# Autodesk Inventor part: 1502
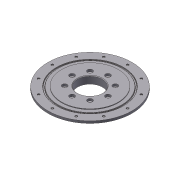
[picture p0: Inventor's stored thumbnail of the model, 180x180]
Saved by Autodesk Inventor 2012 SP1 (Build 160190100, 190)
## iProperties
Created: 2012-02
Part Number: 1502
Material: Aluminum-6061
Document SubType Name: Modeling
Designer: LACO
Density: 2.71 g/cm^3
Mass: 1442.59 g
Surface Area: 1107.25 cm^2
Volume: 532.323 cm^3
Author: LACO
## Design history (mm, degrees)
sketch "Sketch1"
  geometry: L1 (0, 0)-(-139.7, 0); L2 (-120.65, -8.382)-(-60.96, -8.382); L3 (-60.96, -8.382)-(-60.96, -21.082); L4 (-60.96, -21.082)-(-35.56, -21.082); L5 (-35.56, -21.082)-(-35.56, 0); L6 (0, 0)-(0, -15.838); L7 (-120.65, -8.382)-(-120.65, -2.032); L8 (-120.65, -2.032)-(-81.153, -2.032); L9 (-81.153, -2.032)-(-81.153, 0); L10 (-35.56, 0)-(-81.153, 0)
  constraints: 20 end point, 4 perpendicular, 3 parallel, 2 point on line, 1 horizontal
  dimensions: "d1" = 71.12 diameter of L5 L6; "d2" = 121.92 diameter of L3 L6; "d4" = 12.7 distance between parallel lines of L4 L2; "d6" = 2.032 distance between parallel lines of L8 L1; "d7" = 162.306 diameter of L9 L6; "d8" = 241.3 diameter of L7 L6; "d38" = 6.35 distance between parallel lines of L2 L8
revolve "Revolution1" sketch "Sketch1" stored, may be unused: angle "d9" = 90 deg
chamfer "Chamfer1" distance "d21" = 1.5875; stored, may be unused: second distance "d22" = 3.175, angle "d23" = 45 deg
sketch "Sketch2"
  geometry: L1 (0, 0)-(51.435, 0); C1 r 60.96 at (0, 0); C2 r 81.153 at (0, 0) reference; C3 r 37.147 at (0, 0) reference
  constraints: 2 end point, 1 centre point, 1 coincident, 1 horizontal
  dimensions: "d10" = 51.435 distance of L1.start L1.end
hole "Hole1" sketch "Sketch2" at (51.435, 0) diameter "d11" = 5.1054; stored, may be unused: countersink angle "d15" = 100 deg, drill point angle "d17" = 118 deg; dims "d12" = 19.05, "d13" = 14.3002, "d14" = 6.35, "d16" = 25.4
pattern_circular "Circular Pattern1" dims angle "d19" = 360 deg
sketch "Sketch3"
  geometry: L1 (0, 0)-(107.95, 0); C1 r 60.96 at (0, 0) reference; 1 further point
  constraints: 2 end point, 1 coincident, 1 horizontal
  dimensions: "d24" = 107.95 distance of L1.start L1.end
hole "Hole2" sketch "Sketch3" at (107.95, 0) diameter "d25" = 6.7564; stored, may be unused: countersink angle "d29" = 82 deg, drill point angle "d31" = 118 deg; dims "d26" = 19.05, "d27" = 15.875, "d28" = 4.826, "d30" = 25.4
pattern_circular "Circular Pattern2" dims angle "d33" = 360 deg
sketch "Sketch4"
  geometry: L1 (-2.032, -120.65)-(-2.032, 120.65) reference; L2 (-8.382, -120.65)-(-8.382, 120.65) reference; L3 (-2.667, 95.682)-(-4.039, 95.682); L4 (-4.674, 95.047)-(-4.674, 92.227); L5 (-4.039, 91.592)-(-2.667, 91.592); L6 (-2.032, 96.317)-(-2.032, 90.957); L7 (-4.674, 93.637)-(-2.032, 93.637); L8 (-13.868, 0)-(2.311, 0) reference; A1 r 0.635 centre (-4.039, 95.047) between (-4.039, 95.682) and (-4.674, 95.047); A2 r 0.635 centre (-4.039, 92.227) between (-4.674, 92.227) and (-4.039, 91.592); A3 r 0.635 centre (-2.667, 96.317) between (-2.667, 95.682) and (-2.032, 96.317); A4 r 0.635 centre (-2.667, 90.957) between (-2.032, 90.957) and (-2.667, 91.592); 3 further points
  constraints: 10 end point, 8 point on circle, 8 tangent, 4 centre point, 4 point on line, 3 perpendicular, 2 collinear, 2 equal radius, 2 midpoint
  dimensions: "d39" = 0.635 radius of A1; "d40" = 0.635 radius of A3; "d41" = 4.0894 distance between parallel lines of L5 L3; "d42" = 2.6416 distance between parallel lines of L4 L1; "d43" = 93.6371 distance from line of point (0, 0) L7
revolve "Revolution2" sketch "Sketch4" stored, may be unused: angle "d44" = 90 deg
sketch "Sketch5"
  geometry: L1 (59.372, -21.082)-(-59.372, -21.082) reference; L2 (-60.96, -19.495)-(-60.96, -8.382) reference; L3 (-48.882, -21.082)-(-53.988, -21.082) reference; L4 (-48.882, -6.35)-(-53.988, -6.35) reference; L5 (60.96, -8.382)-(-60.96, -8.382) reference; L6 (-60.96, -19.495)-(60.96, -19.495) reference; L7 (-53.988, -21.082)-(-53.988, -6.35) reference; L8 (-48.882, -21.082)-(-48.882, -6.35) reference; L9 (-59.169, -20.447)-(-59.169, -19.075); L10 (-58.534, -18.44)-(-55.715, -18.44); L11 (-55.08, -19.075)-(-55.08, -20.447); L12 (-59.804, -21.082)-(-54.445, -21.082); L13 (-57.125, -18.44)-(-57.125, -21.082); L14 (0, -29.266)-(0, 4.878) reference; A1 r 0.635 centre (-59.804, -20.447) between (-59.804, -21.082) and (-59.169, -20.447); A2 r 0.635 centre (-54.445, -20.447) between (-55.08, -20.447) and (-54.445, -21.082); A3 r 0.635 centre (-55.715, -19.075) between (-55.08, -19.075) and (-55.715, -18.44); A4 r 0.635 centre (-58.534, -19.075) between (-58.534, -18.44) and (-59.169, -19.075); 1 further point
  constraints: 10 end point, 8 point on circle, 8 tangent, 4 centre point, 3 equal radius, 2 midpoint, 1 collinear, 1 parallel, 1 perpendicular
  dimensions: "d45" = 0.635 radius of A1; "d46" = 2.6416 distance between parallel lines of L10 L12; "d47" = 4.0894 distance between parallel lines of L11 L9; "d48" = 57.1246 distance from line of point (0, 0) L13
revolve "Revolution3" sketch "Sketch5" stored, may be unused: angle "d49" = 90 deg
body "Solid1"
node "Projected Loop1"
node "Projected Loop2"
